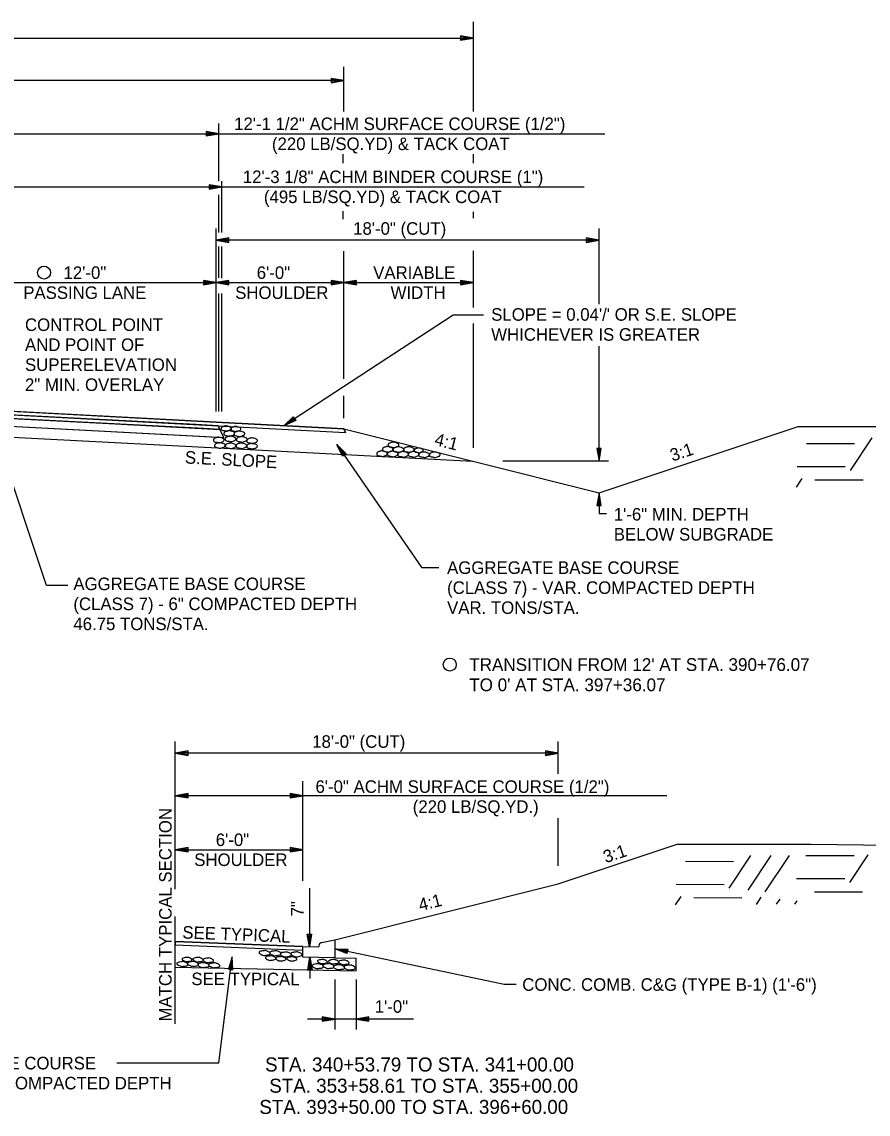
# Model space of a CAD drawing. Extents: x 1398183 to 1398373, y 1967240 to 1968889.
# Drawn here: x 1398264.5 to 1398304.3, y 1968370.6 to 1968421.9 of the extents above; entities that cross this region are included whole.
import ezdxf

# ---------------------------------------------------------------- set-up
doc = ezdxf.new("R2010")
doc.units = 0
for name, color, linetype in [('1', 7, 'Continuous'), ('10', 7, 'Continuous'), ('19', 7, 'Continuous'), ('42', 7, 'Continuous'), ('9', 7, 'Continuous'), ('Default', 7, 'Continuous'), ('Level 1', 7, 'Continuous')]:
    doc.layers.add(name, color=color, linetype=linetype)

# ---------------------------------------------------------------- blocks, each defined once
blk = doc.blocks.new('ROCKS')
at = {"layer": '1'}
blk.add_spline([(0.013, 0.06), (0.053, 0.053), (0.107, 0.033), (0.133, 0.013), (0.133, -0.007), (0.12, -0.033), (0.107, -0.04), (0.073, -0.053), (0.033, -0.067), (0.013, -0.067), (-0.02, -0.06), (-0.06, -0.053), (-0.087, -0.047), (-0.113, -0.02), (-0.113, -0.007), (-0.107, 0.02), (-0.087, 0.033), (-0.067, 0.047), (-0.033, 0.053), (-0.02, 0.06), (0.013, 0.06)], degree=3, dxfattribs=at)

msp = doc.modelspace()

# ---------------------------------------------------------------- linework, layer by layer
at = {"layer": '10'}
for centre in [(1398265.578, 1968410.12), (1398284.652, 1968391.694)]:
    msp.add_circle(centre, 0.306, dxfattribs=at)
at = {"layer": '19'}
for p, q in [((1398285.763, 1968417.695), (1398285.763, 1968421.911)), ((1398223.852, 1968421.15), (1398285.763, 1968421.15)), ((1398285.163, 1968421.255), (1398285.163, 1968421.045)), ((1398285.763, 1968421.15), (1398285.163, 1968421.255)), ((1398285.603, 1968421.165), (1398285.163, 1968421.2)), ((1398285.163, 1968421.045), (1398285.763, 1968421.15)), ((1398285.163, 1968421.095), (1398285.603, 1968421.135)), ((1398279.672, 1968417.695), (1398279.672, 1968419.797)), ((1398279.072, 1968419.255), (1398279.072, 1968419.045)), ((1398279.672, 1968419.15), (1398279.072, 1968419.255)), ((1398279.672, 1968419.15), (1398229.672, 1968419.15)), ((1398279.512, 1968419.165), (1398279.072, 1968419.2)), ((1398279.072, 1968419.045), (1398279.672, 1968419.15)), ((1398279.072, 1968419.095), (1398279.512, 1968419.135)), ((1398273.199, 1968416.755), (1398273.199, 1968416.545)), ((1398273.799, 1968416.65), (1398273.199, 1968416.755)), ((1398273.639, 1968416.665), (1398273.199, 1968416.7)), ((1398273.8, 1968414.417), (1398273.8, 1968417.132)), ((1398261.672, 1968416.65), (1398291.943, 1968416.65)), ((1398273.199, 1968416.545), (1398273.799, 1968416.65)), ((1398273.199, 1968416.595), (1398273.639, 1968416.635)), ((1398279.64, 1968415.267), (1398279.64, 1968415.684)), ((1398285.764, 1968415.274), (1398285.764, 1968415.69)), ((1398237.672, 1968414.15), (1398290.974, 1968414.15)), ((1398273.337, 1968414.255), (1398273.337, 1968414.045)), ((1398273.937, 1968414.15), (1398273.337, 1968414.255)), ((1398273.777, 1968414.165), (1398273.337, 1968414.2)), ((1398273.337, 1968414.045), (1398273.937, 1968414.15)), ((1398273.337, 1968414.095), (1398273.777, 1968414.135)), ((1398273.937, 1968412.009), (1398273.937, 1968414.415)), ((1398273.8, 1968412.009), (1398273.8, 1968413.774)), ((1398279.64, 1968412.641), (1398279.64, 1968413.013)), ((1398285.763, 1968412.687), (1398285.763, 1968412.977)), ((1398273.672, 1968403.59), (1398273.672, 1968412.197)), ((1398291.672, 1968408.637), (1398291.672, 1968412.197)), ((1398274.272, 1968411.755), (1398273.672, 1968411.65)), ((1398289.672, 1968411.65), (1398273.672, 1968411.65)), ((1398273.672, 1968411.65), (1398274.272, 1968411.545)), ((1398291.672, 1968411.65), (1398273.672, 1968411.65)), ((1398274.272, 1968411.7), (1398273.832, 1968411.665)), ((1398273.832, 1968411.635), (1398274.272, 1968411.595)), ((1398274.272, 1968411.545), (1398274.272, 1968411.755)), ((1398291.072, 1968411.755), (1398291.072, 1968411.545)), ((1398291.672, 1968411.65), (1398291.072, 1968411.755)), ((1398291.512, 1968411.665), (1398291.072, 1968411.7)), ((1398291.072, 1968411.545), (1398291.672, 1968411.65)), ((1398291.072, 1968411.595), (1398291.512, 1968411.635)), ((1398273.8, 1968409.869), (1398273.8, 1968411.357)), ((1398273.937, 1968409.867), (1398273.937, 1968411.356)), ((1398279.672, 1968405.131), (1398279.672, 1968411.135)), ((1398285.763, 1968408.484), (1398285.763, 1968411.153)), ((1398261.672, 1968409.65), (1398273.672, 1968409.65)), ((1398273.072, 1968409.755), (1398273.072, 1968409.545)), ((1398273.672, 1968409.65), (1398273.072, 1968409.755)), ((1398273.512, 1968409.665), (1398273.072, 1968409.7)), ((1398273.072, 1968409.545), (1398273.672, 1968409.65)), ((1398273.072, 1968409.595), (1398273.512, 1968409.635)), ((1398274.272, 1968409.755), (1398273.672, 1968409.65)), ((1398273.672, 1968409.65), (1398279.672, 1968409.65)), ((1398273.672, 1968409.65), (1398274.272, 1968409.545)), ((1398274.272, 1968409.7), (1398273.832, 1968409.665)), ((1398273.832, 1968409.635), (1398274.272, 1968409.595)), ((1398274.272, 1968409.545), (1398274.272, 1968409.755)), ((1398279.072, 1968409.755), (1398279.072, 1968409.545)), ((1398279.672, 1968409.65), (1398279.072, 1968409.755)), ((1398279.512, 1968409.665), (1398279.072, 1968409.7)), ((1398279.072, 1968409.545), (1398279.672, 1968409.65)), ((1398279.072, 1968409.595), (1398279.512, 1968409.635)), ((1398280.268, 1968409.755), (1398279.668, 1968409.65)), ((1398279.668, 1968409.65), (1398285.763, 1968409.65)), ((1398279.668, 1968409.65), (1398280.268, 1968409.545)), ((1398280.268, 1968409.7), (1398279.828, 1968409.665)), ((1398279.828, 1968409.635), (1398280.268, 1968409.595)), ((1398280.268, 1968409.545), (1398280.268, 1968409.755)), ((1398285.163, 1968409.755), (1398285.163, 1968409.545)), ((1398285.763, 1968409.65), (1398285.163, 1968409.755)), ((1398285.603, 1968409.665), (1398285.163, 1968409.7)), ((1398285.163, 1968409.545), (1398285.763, 1968409.65)), ((1398285.163, 1968409.595), (1398285.603, 1968409.635)), ((1398273.8, 1968403.59), (1398273.8, 1968409.138)), ((1398273.937, 1968403.59), (1398273.937, 1968409.135)), ((1398284.809, 1968408.125), (1398276.851, 1968402.922)), ((1398286.247, 1968408.125), (1398284.809, 1968408.125)), ((1398285.763, 1968401.889), (1398285.763, 1968407.722)), ((1398291.672, 1968401.259), (1398291.672, 1968406.666)), ((1398279.672, 1968403.272), (1398279.672, 1968404.329)), ((1398261.672, 1968403.394), (1398273.842, 1968402.75)), ((1398273.1, 1968402.79), (1398262.252, 1968403.362)), ((1398276.851, 1968402.922), (1398277.296, 1968403.338)), ((1398277.296, 1968403.338), (1398277.409, 1968403.162)), ((1398261.672, 1968403.019), (1398274.032, 1968402.371)), ((1398273.757, 1968402.92), (1398273.842, 1968402.75)), ((1398277.409, 1968403.162), (1398276.851, 1968402.922)), ((1398276.978, 1968403.019), (1398277.323, 1968403.292)), ((1398277.382, 1968403.203), (1398276.993, 1968402.995)), ((1398291.672, 1968399.772), (1398301.039, 1968402.895)), ((1398265.69, 1968395.413), (1398263.308, 1968402.566)), ((1398273.842, 1968402.75), (1398273.1, 1968402.79)), ((1398273.177, 1968402.417), (1398274.032, 1968402.371)), ((1398273.842, 1968402.75), (1398274.032, 1968402.371)), ((1398274.032, 1968402.371), (1398273.842, 1968402.75)), ((1398279.672, 1968402.772), (1398291.672, 1968399.772)), ((1398279.672, 1968402.772), (1398279.757, 1968402.602)), ((1398279.603, 1968401.492), (1398279.35, 1968402.044)), ((1398279.35, 1968402.044), (1398279.775, 1968401.608)), ((1398283.354, 1968396.249), (1398279.354, 1968402.038)), ((1398279.643, 1968401.52), (1398279.426, 1968401.903)), ((1398279.45, 1968401.92), (1398279.73, 1968401.581)), ((1398291.777, 1968401.859), (1398291.567, 1968401.859)), ((1398291.567, 1968401.859), (1398291.672, 1968401.259)), ((1398291.617, 1968401.859), (1398291.657, 1968401.419)), ((1398291.672, 1968401.259), (1398291.777, 1968401.859)), ((1398291.687, 1968401.419), (1398291.722, 1968401.859)), ((1398279.775, 1968401.608), (1398279.603, 1968401.492)), ((1398291.672, 1968399.771), (1398291.567, 1968399.171)), ((1398291.777, 1968399.171), (1398291.672, 1968399.771)), ((1398291.657, 1968399.611), (1398291.622, 1968399.171)), ((1398291.727, 1968399.171), (1398291.687, 1968399.611)), ((1398291.567, 1968399.171), (1398291.777, 1968399.171)), ((1398284.144, 1968396.249), (1398283.354, 1968396.249)), ((1398266.703, 1968395.413), (1398265.69, 1968395.413)), ((1398271.747, 1968381.14), (1398271.747, 1968388.077)), ((1398289.747, 1968386.555), (1398289.747, 1968388.077)), ((1398272.347, 1968387.635), (1398271.747, 1968387.53)), ((1398289.747, 1968387.53), (1398271.747, 1968387.53)), ((1398271.747, 1968387.53), (1398272.347, 1968387.425)), ((1398272.347, 1968387.58), (1398271.907, 1968387.545)), ((1398271.907, 1968387.515), (1398272.347, 1968387.475)), ((1398272.347, 1968387.425), (1398272.347, 1968387.635)), ((1398289.147, 1968387.635), (1398289.147, 1968387.425)), ((1398289.747, 1968387.53), (1398289.147, 1968387.635)), ((1398289.587, 1968387.545), (1398289.147, 1968387.58)), ((1398289.147, 1968387.425), (1398289.747, 1968387.53)), ((1398289.147, 1968387.475), (1398289.587, 1968387.515)), ((1398277.747, 1968381.525), (1398277.747, 1968386.219)), ((1398272.347, 1968385.635), (1398271.747, 1968385.53)), ((1398294.866, 1968385.53), (1398271.747, 1968385.53)), ((1398271.747, 1968385.53), (1398272.347, 1968385.425)), ((1398272.347, 1968385.58), (1398271.907, 1968385.545)), ((1398271.907, 1968385.515), (1398272.347, 1968385.475)), ((1398272.347, 1968385.425), (1398272.347, 1968385.635)), ((1398277.147, 1968385.635), (1398277.147, 1968385.425)), ((1398277.747, 1968385.53), (1398277.147, 1968385.635)), ((1398277.587, 1968385.545), (1398277.147, 1968385.58)), ((1398277.147, 1968385.425), (1398277.747, 1968385.53)), ((1398277.147, 1968385.475), (1398277.587, 1968385.515)), ((1398289.747, 1968382.236), (1398289.747, 1968384.47)), ((1398272.347, 1968383.095), (1398271.747, 1968382.99)), ((1398271.747, 1968382.99), (1398277.747, 1968382.99)), ((1398271.747, 1968382.99), (1398272.347, 1968382.885)), ((1398272.347, 1968383.04), (1398271.907, 1968383.005)), ((1398271.907, 1968382.975), (1398272.347, 1968382.935)), ((1398272.347, 1968382.885), (1398272.347, 1968383.095)), ((1398277.147, 1968383.095), (1398277.147, 1968382.885)), ((1398277.747, 1968382.99), (1398277.147, 1968383.095)), ((1398277.587, 1968383.005), (1398277.147, 1968383.04)), ((1398277.147, 1968382.885), (1398277.747, 1968382.99)), ((1398277.147, 1968382.935), (1398277.587, 1968382.975)), ((1398289.747, 1968381.386), (1398295.345, 1968383.252)), ((1398279.247, 1968378.761), (1398289.747, 1968381.386)), ((1398278.053, 1968381.184), (1398278.053, 1968378.419)), ((1398271.747, 1968374.802), (1398271.747, 1968379.853)), ((1398277.948, 1968379.019), (1398278.158, 1968379.019)), ((1398278.053, 1968378.419), (1398277.948, 1968379.019)), ((1398278.038, 1968378.579), (1398277.998, 1968379.019)), ((1398278.158, 1968379.019), (1398278.053, 1968378.419)), ((1398278.103, 1968379.019), (1398278.068, 1968378.579)), ((1398278.627, 1968378.624), (1398279.247, 1968378.761)), ((1398279.247, 1968378.761), (1398279.247, 1968377.913)), ((1398277.747, 1968377.943), (1398277.747, 1968378.443)), ((1398277.747, 1968378.443), (1398278.497, 1968378.428)), ((1398278.497, 1968378.428), (1398278.497, 1968378.461)), ((1398287.207, 1968376.653), (1398279.247, 1968378.337)), ((1398279.811, 1968378.111), (1398279.247, 1968378.337)), ((1398279.247, 1968378.337), (1398279.856, 1968378.315)), ((1398279.821, 1968378.16), (1398279.399, 1968378.288)), ((1398279.405, 1968378.316), (1398279.842, 1968378.264)), ((1398279.856, 1968378.315), (1398279.811, 1968378.111)), ((1398273.792, 1968372.968), (1398274.43, 1968377.954)), ((1398274.43, 1968377.954), (1398274.25, 1968377.372)), ((1398274.398, 1968377.798), (1398274.303, 1968377.368)), ((1398274.408, 1968377.354), (1398274.426, 1968377.794)), ((1398274.457, 1968377.347), (1398274.43, 1968377.954)), ((1398279.247, 1968377.913), (1398277.747, 1968377.943)), ((1398277.976, 1968377.336), (1398278.081, 1968377.936)), ((1398278.026, 1968377.336), (1398278.066, 1968377.776)), ((1398278.081, 1968377.936), (1398278.186, 1968377.336)), ((1398278.081, 1968377.936), (1398278.081, 1968376.936)), ((1398278.096, 1968377.776), (1398278.131, 1968377.336)), ((1398280.247, 1968377.305), (1398280.247, 1968377.893)), ((1398274.25, 1968377.372), (1398274.457, 1968377.347)), ((1398278.186, 1968377.336), (1398277.976, 1968377.336)), ((1398279.247, 1968376.885), (1398279.247, 1968374.538)), ((1398280.247, 1968376.885), (1398280.247, 1968374.538)), ((1398287.777, 1968376.653), (1398287.207, 1968376.653)), ((1398278.647, 1968375.135), (1398278.647, 1968374.925)), ((1398279.247, 1968375.03), (1398278.647, 1968375.135)), ((1398280.847, 1968375.135), (1398280.247, 1968375.03)), ((1398280.847, 1968374.925), (1398280.847, 1968375.135)), ((1398282.952, 1968375.03), (1398277.972, 1968375.03)), ((1398279.087, 1968375.045), (1398278.647, 1968375.08)), ((1398278.647, 1968374.925), (1398279.247, 1968375.03)), ((1398278.647, 1968374.975), (1398279.087, 1968375.015)), ((1398280.247, 1968375.03), (1398280.847, 1968374.925)), ((1398280.847, 1968375.08), (1398280.407, 1968375.045)), ((1398280.407, 1968375.015), (1398280.847, 1968374.975)), ((1398268.994, 1968372.968), (1398273.792, 1968372.968))]:
    msp.add_line(p, q, dxfattribs=at)
for points in [[(1398229.587, 1968405.252), (1398237.672, 1968404.827), (1398249.673, 1968404.196), (1398273.757, 1968402.92), (1398279.757, 1968402.602), (1398279.672, 1968402.772), (1398273.672, 1968403.09), (1398249.673, 1968404.362), (1398237.672, 1968404.998), (1398229.672, 1968405.422)], [(1398261.672, 1968403.56), (1398261.672, 1968403.394), (1398262.509, 1968403.349), (1398271.364, 1968402.881), (1398273.842, 1968402.75), (1398273.757, 1968402.92), (1398272.718, 1968402.976), (1398262.451, 1968403.519)], [(1398271.747, 1968378.516), (1398277.747, 1968378.276), (1398277.747, 1968378.443), (1398271.747, 1968378.683)]]:
    msp.add_lwpolyline(points, close=True, dxfattribs=at)
for points in [[(1398229.672, 1968405.422), (1398237.672, 1968404.998), (1398249.673, 1968404.362), (1398261.672, 1968403.726), (1398273.672, 1968403.09), (1398279.672, 1968402.772)], [(1398229.587, 1968405.252), (1398249.673, 1968404.196), (1398273.757, 1968402.92), (1398279.757, 1968402.602)], [(1398261.672, 1968403.019), (1398262.201, 1968402.99), (1398273.177, 1968402.417)], [(1398261.672, 1968402.519), (1398274.032, 1968401.871), (1398285.725, 1968401.259)], [(1398271.747, 1968378.683), (1398277.747, 1968378.443)], [(1398271.747, 1968378.516), (1398277.747, 1968378.276)], [(1398279.247, 1968377.913), (1398280.247, 1968377.893)], [(1398271.747, 1968377.475), (1398280.247, 1968377.305)]]:
    msp.add_lwpolyline(points, dxfattribs=at)
msp.add_arc((1398278.664, 1968378.461), 0.167, 102.5288, 180, dxfattribs=at)
at = {"layer": '42'}
for points in [[(1398301.039, 1968402.895), (1398307.325, 1968402.895), (1398311.041, 1968402.844)], [(1398295.345, 1968383.252), (1398301.631, 1968383.252), (1398305.347, 1968383.202)]]:
    msp.add_lwpolyline(points, dxfattribs=at)
at = {"layer": '9'}
for p, q in [((1398304.494, 1968402.357), (1398303.471, 1968400.823)), ((1398303.687, 1968402.067), (1398301.425, 1968402.073)), ((1398303.248, 1968400.989), (1398300.986, 1968400.995)), ((1398301.211, 1968400.439), (1398300.947, 1968400.043)), ((1398304.085, 1968400.363), (1398301.823, 1968400.368)), ((1398297.992, 1968382.424), (1398295.731, 1968382.43)), ((1398298.8, 1968382.714), (1398297.777, 1968381.18)), ((1398299.752, 1968382.72), (1398298.667, 1968381.093)), ((1398300.612, 1968382.725), (1398299.465, 1968381.004)), ((1398303.664, 1968382.697), (1398301.402, 1968382.703)), ((1398304.31, 1968382.745), (1398303.449, 1968381.453)), ((1398297.554, 1968381.346), (1398295.292, 1968381.352)), ((1398303.225, 1968381.619), (1398300.963, 1968381.625)), ((1398295.517, 1968380.797), (1398295.253, 1968380.4)), ((1398299.281, 1968380.762), (1398299.054, 1968380.422)), ((1398304.063, 1968380.993), (1398301.801, 1968380.999)), ((1398298.391, 1968380.72), (1398296.129, 1968380.726)), ((1398300.171, 1968380.674), (1398300.006, 1968380.427)), ((1398300.969, 1968380.586), (1398300.866, 1968380.432))]:
    msp.add_line(p, q, dxfattribs=at)
at = {"layer": 'Default'}
msp.add_line((1398292.123, 1968401.259), (1398287.15, 1968401.259), dxfattribs=at)
msp.add_lwpolyline([(1398291.672, 1968399.771), (1398291.672, 1968398.791), (1398292.015, 1968398.791)], dxfattribs=at)

# ---------------------------------------------------------------- block references
at = {"layer": 'Level 1'}
for p, xscale, yscale, rotation in [((1398274.123, 1968402.8), 1.8771740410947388, 1.8771740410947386, -0.173618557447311), ((1398274.58, 1968402.775), 1.849824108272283, 1.8498241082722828, -0.17361855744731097), ((1398273.774, 1968402.259), 2.011654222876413, 2.0116542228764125, -0.17361855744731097), ((1398274.266, 1968402.566), 2.011654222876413, 2.0116542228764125, -0.17361855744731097), ((1398274.32, 1968402.311), 2.011654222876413, 2.0116542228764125, -0.17361855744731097), ((1398274.743, 1968402.551), 2.011654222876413, 2.0116542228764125, -0.17361855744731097), ((1398274.853, 1968402.288), 2.011654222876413, 2.0116542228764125, -0.17361855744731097), ((1398275.342, 1968402.227), 2.011654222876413, 2.0116542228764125, -0.17361855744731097), ((1398273.825, 1968402.002), 2.011654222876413, 2.0116542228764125, -0.17361855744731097), ((1398274.329, 1968401.984), 2.011654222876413, 2.0116542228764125, -0.17361855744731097), ((1398274.835, 1968401.987), 2.011654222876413, 2.0116542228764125, -0.17361855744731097), ((1398275.338, 1968401.969), 2.011654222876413, 2.0116542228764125, -0.17361855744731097), ((1398281.716, 1968401.822), 2.011654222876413, 2.0116542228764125, -0.17361855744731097), ((1398281.985, 1968402.029), 2.011654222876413, 2.0116542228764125, -0.17361855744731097), ((1398282.216, 1968401.81), 2.011654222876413, 2.0116542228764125, -0.17361855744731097), ((1398282.712, 1968401.81), 2.011654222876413, 2.0116542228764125, -0.17361855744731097), ((1398283.173, 1968401.77), 1.7335100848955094, 1.7335100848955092, -0.173618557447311), ((1398281.446, 1968401.615), 2.011654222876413, 2.0116542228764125, -0.17361855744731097), ((1398281.95, 1968401.604), 2.011654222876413, 2.0116542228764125, -0.17361855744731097), ((1398282.442, 1968401.586), 2.011654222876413, 2.0116542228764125, -0.17361855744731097), ((1398282.932, 1968401.586), 2.011654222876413, 2.0116542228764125, -0.17361855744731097), ((1398283.425, 1968401.567), 2.011654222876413, 2.0116542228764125, -0.17361855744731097), ((1398283.928, 1968401.567), 2.011654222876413, 2.0116542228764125, -0.17361855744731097), ((1398275.931, 1968378.13), 2.0116542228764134, -2.011654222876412, -4.336484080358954), ((1398276.436, 1968378.119), 2.0116542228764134, -2.011654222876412, -4.336484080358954), ((1398276.931, 1968378.063), 2.0116542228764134, -2.011654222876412, -4.336484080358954), ((1398277.428, 1968378.067), 2.0116542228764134, -2.011654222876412, -4.336484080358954), ((1398272.103, 1968377.624), 2.0116542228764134, -2.011654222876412, 175.66351591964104), ((1398272.318, 1968377.837), 1.773922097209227, -1.7739220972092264, 175.66351591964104), ((1398272.601, 1968377.627), 2.0116542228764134, -2.011654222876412, 175.66351591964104), ((1398272.839, 1968377.83), 1.851115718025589, -1.8511157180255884, 175.66351591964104), ((1398273.096, 1968377.572), 2.0116542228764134, -2.011654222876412, 175.66351591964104), ((1398273.321, 1968377.8), 1.8866375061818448, -1.886637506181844, 175.66351591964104), ((1398273.6, 1968377.561), 2.0116542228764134, -2.011654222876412, 175.66351591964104), ((1398276.21, 1968377.891), 1.8866375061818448, -1.886637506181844, -4.336484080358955), ((1398276.693, 1968377.86), 1.851115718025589, -1.8511157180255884, -4.336484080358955), ((1398277.214, 1968377.853), 1.773922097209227, -1.7739220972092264, -4.336484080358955), ((1398278.471, 1968377.523), 2.0116542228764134, -2.011654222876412, 175.66351591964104), ((1398278.686, 1968377.737), 1.773922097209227, -1.7739220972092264, 175.66351591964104), ((1398278.969, 1968377.526), 2.0116542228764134, -2.011654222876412, 175.66351591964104), ((1398279.207, 1968377.729), 1.851115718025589, -1.8511157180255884, 175.66351591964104), ((1398279.689, 1968377.699), 1.8866375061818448, -1.886637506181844, 175.66351591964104), ((1398279.463, 1968377.471), 2.0116542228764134, -2.011654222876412, 175.66351591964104), ((1398279.968, 1968377.46), 2.0116542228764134, -2.011654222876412, 175.66351591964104)]:
    msp.add_blockref('ROCKS', p, dxfattribs=dict(at, xscale=xscale, yscale=yscale, rotation=rotation))

# ---------------------------------------------------------------- texts
at = {"layer": '10'}
for s, height, p in [('18\'-0" (CUT)', 0.59001, (1398280.112, 1968411.902)), ('12\'-0"', 0.59, (1398266.495, 1968409.825)), ('6\'-0"', 0.59, (1398275.578, 1968409.825)), ('VARIABLE', 0.59, (1398281.054, 1968409.825)), ('PASSING LANE', 0.59001, (1398264.601, 1968408.885)), ('SHOULDER', 0.59, (1398274.565, 1968408.885)), ('WIDTH', 0.59, (1398281.872, 1968408.885)), ('CONTROL POINT', 0.59001, (1398264.682, 1968407.378)), ('AND POINT OF ', 0.59001, (1398264.682, 1968406.438)), ('SUPERELEVATION', 0.59001, (1398264.682, 1968405.498)), ('2" MIN. OVERLAY', 0.59001, (1398264.682, 1968404.558)), ('18\'-0" (CUT)', 0.59001, (1398278.187, 1968387.782)), ('6\'-0" ACHM SURFACE COURSE (1/2")', 0.59001, (1398278.341, 1968385.663)), ('(220 LB/SQ.YD.)', 0.59001, (1398282.913, 1968384.723)), ('6\'-0"', 0.59, (1398273.653, 1968383.165)), ('SHOULDER', 0.59, (1398272.64, 1968382.225)), ('1\'-0"', 0.59, (1398281.126, 1968375.325))]:
    msp.add_text(s, height=height, dxfattribs=at).set_placement(p)
for s, height, rotation, p in [('4:1', 0.59, 345.9638, (1398283.897, 1968402.02)), ('3:1', 0.59, 18.4349, (1398295.125, 1968401.234)), ('1\'-6" MIN. DEPTH', 0.59001, 360, (1398292.366, 1968398.466)), ('BELOW SUBGRADE', 0.59001, 360, (1398292.366, 1968397.526)), ('MATCH TYPICAL SECTION', 0.59001, 90, (1398271.576, 1968374.914)), ('3:1', 0.59, 18.4349, (1398291.986, 1968382.354)), ('4:1', 0.59, 14.0362, (1398283.266, 1968380.098)), ('SEE TYPICAL', 0.59001, 357.7094, (1398272.072, 1968378.82)), ('SEE TYPICAL', 0.59001, 359.948, (1398272.505, 1968376.625))]:
    msp.add_text(s, height=height, rotation=rotation, dxfattribs=at).set_placement(p)
at = {"layer": '19'}
for s, height, p in [("SLOPE = 0.04'/' OR S.E. SLOPE", 0.59001, (1398286.601, 1968407.86)), ('WHICHEVER IS GREATER', 0.59001, (1398286.601, 1968406.92)), ('CONC. COMB. C&G (TYPE B-1) (1\'-6")', 0.59001, (1398288.062, 1968376.358)), ('STA. 340+53.79 TO STA. 341+00.00', 0.65999, (1398275.969, 1968372.564)), ('STA. 353+58.61 TO STA. 355+00.00', 0.65999, (1398276.167, 1968371.567)), ('STA. 393+50.00 TO STA. 396+60.00', 0.65999, (1398275.699, 1968370.569))]:
    msp.add_text(s, height=height, dxfattribs=at).set_placement(p)
for s, height, rotation, p in [('S.E. SLOPE', 0.59, 356.9662, (1398272.19, 1968401.151)), ('AGGREGATE BASE COURSE', 0.59001, 360, (1398284.528, 1968395.957)), ('AGGREGATE BASE COURSE', 0.59001, 360, (1398266.957, 1968395.194)), ('(CLASS 7) - VAR. COMPACTED DEPTH', 0.59001, 360, (1398284.528, 1968395.017)), ('(CLASS 7) - 6" COMPACTED DEPTH', 0.59001, 360, (1398266.957, 1968394.254)), ('VAR. TONS/STA.', 0.59001, 360, (1398284.528, 1968394.077)), ('46.75 TONS/STA.', 0.59001, 360, (1398266.957, 1968393.314)), ('AGGREGATE BASE COURSE', 0.59001, 360, (1398257.109, 1968372.664)), ('(CLASS 7) - VAR. COMPACTED DEPTH', 0.59001, 360, (1398257.109, 1968371.724))]:
    msp.add_text(s, height=height, rotation=rotation, dxfattribs=at).set_placement(p)
at = {"layer": '42'}
for s, height, rotation, p in [('12\'-1 1/2" ACHM SURFACE COURSE (1/2")', 0.59001, 360, (1398274.516, 1968416.822)), ('(220 LB/SQ.YD) & TACK COAT', 0.59001, 360, (1398276.293, 1968415.882)), ('12\'-3 1/8" ACHM BINDER COURSE (1")', 0.59001, 360, (1398274.924, 1968414.331)), ('(495 LB/SQ.YD) & TACK COAT', 0.59001, 360, (1398275.916, 1968413.391)), ('7"', 0.59, 90, (1398277.785, 1968379.858))]:
    msp.add_text(s, height=height, rotation=rotation, dxfattribs=at).set_placement(p)
for s, p in [("TRANSITION FROM 12' AT STA. 390+76.07", (1398285.569, 1968391.394)), ("TO 0' AT STA. 397+36.07", (1398285.569, 1968390.444))]:
    msp.add_text(s, height=0.6, dxfattribs=at).set_placement(p)

doc.saveas('drawing.dxf')
